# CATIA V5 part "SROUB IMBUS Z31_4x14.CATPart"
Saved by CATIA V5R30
Part number: SROUB IMBUS Z31/4x14
Bounding box of the stored display mesh (mm): x -4 to 14, y -3.49 to 3.49, z -3.5 to 3.5
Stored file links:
  C:\Users\ondra\Desktop\PŘÍLOHA P III\CATIA\SROUB IMBUS Z31_4x14.CATPart
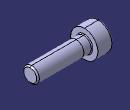
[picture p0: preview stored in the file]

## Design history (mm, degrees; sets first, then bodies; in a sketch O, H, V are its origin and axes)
Set1
  DatumSurface1 to DatumSurface30 "Z31/4x14"
  Join1: Elements (DatumSurface1; DatumSurface2; DatumSurface3; DatumSurface4; DatumSurface5; DatumSurface6; DatumSurface7; DatumSurface8; DatumSurface9; DatumSurface10; DatumSurface11; DatumSurface12; DatumSurface13; DatumSurface14; DatumSurface16; DatumSurface17; DatumSurface18; DatumSurface19; DatumSurface20; DatumSurface21; DatumSurface22; DatumSurface23; DatumSurface24; DatumSurface25; DatumSurface26; DatumSurface27; DatumSurface28; DatumSurface29; DatumSurface30)
Body1 (main body)
  CloseSurface1: CloseElement Join1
